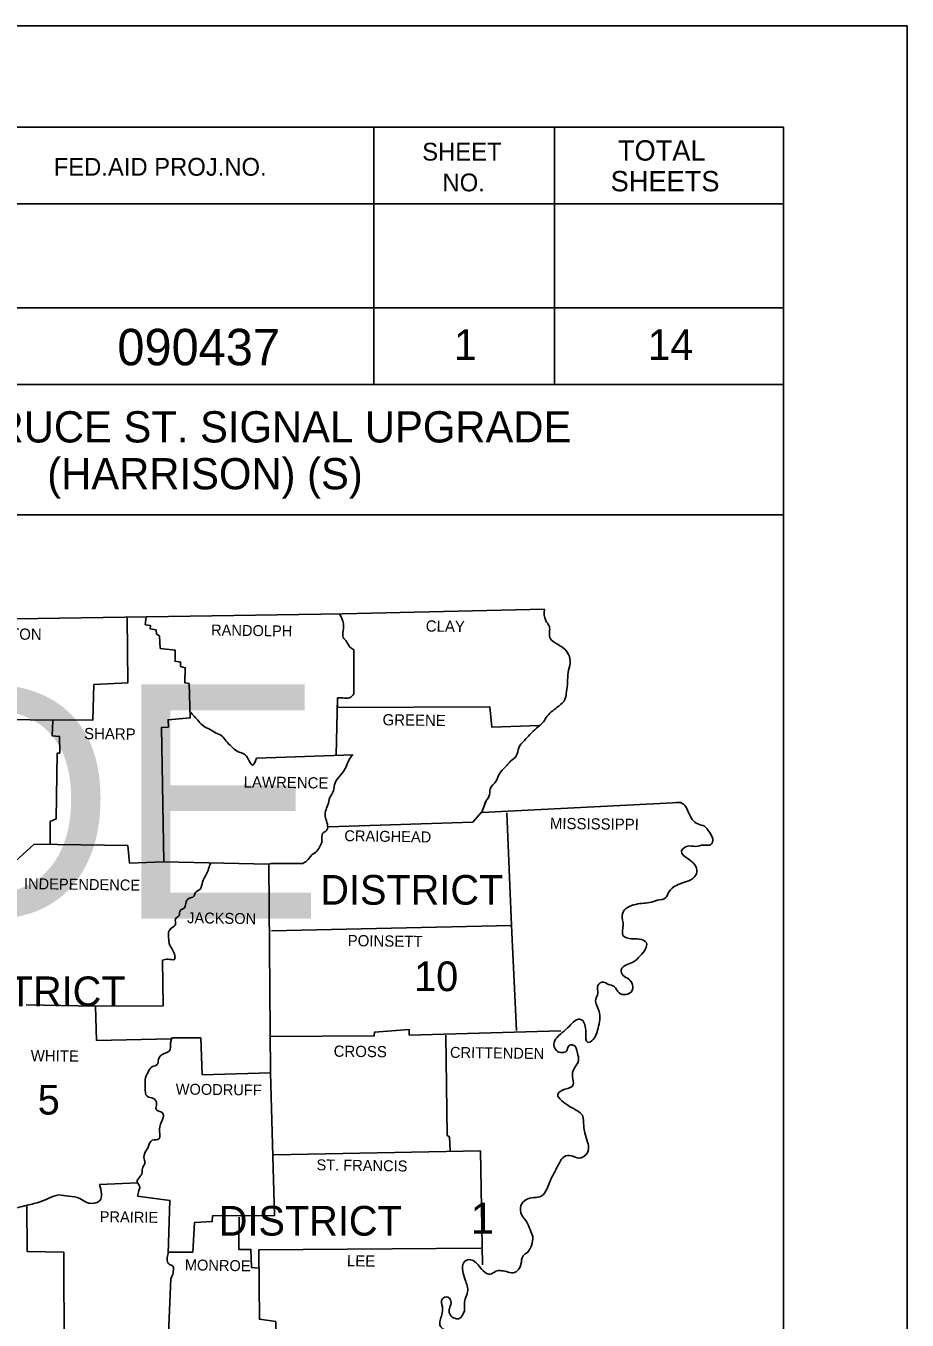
# Model space of a CAD drawing. Extents: x 19118 to 454486, y 1325406 to 1693506.
# Drawn here: x 26754.5 to 27093.1, y 1327042.2 to 1327539.3 of the extents above; entities that cross this region are included whole.
import ezdxf

# ---------------------------------------------------------------- set-up
doc = ezdxf.new("R2010")
doc.units = 0
for name, color, linetype in [('S_CURB', 7, 'Continuous'), ('S_EDGE_PAVEMENT', 7, 'Continuous'), ('S_PAVEMENT_CROWN', 7, 'Continuous'), ('S_SHOULDER', 7, 'Continuous')]:
    doc.layers.add(name, color=color, linetype=linetype)

msp = doc.modelspace()

# ---------------------------------------------------------------- linework, layer by layer
at = {"layer": 'S_CURB'}
for p, q in [((27045.61, 1327471.12), (27045.61, 1327471.12)), ((26929.76, 1327237.18), (26930.96, 1327240.88)), ((26930.06, 1327238.38), (26931.26, 1327241.28)), ((26810.56, 1327150.58), (26821.74, 1327150.58))]:
    msp.add_line(p, q, dxfattribs=at)
for points in [[(26405.17, 1327310.68), (26566.87, 1327310.58), (26708.77, 1327310.88), (26876.16, 1327313.48), (26953.76, 1327315.28)], [(26793.46, 1327312.2), (26793.66, 1327286.98), (26780.66, 1327286.28), (26780.26, 1327272.68), (26707.97, 1327273.08)], [(26800.74, 1327312.31), (26800.36, 1327309.28), (26802.36, 1327308.98), (26802.26, 1327307.78), (26804.56, 1327307.28), (26804.76, 1327305.68), (26805.86, 1327304.98), (26806.16, 1327300.18), (26811.86, 1327299.58), (26811.86, 1327295.28), (26813.96, 1327294.98), (26813.96, 1327293.28), (26815.76, 1327292.78), (26815.66, 1327286.98), (26817.26, 1327286.68), (26817.66, 1327273.58), (26809.16, 1327272.78), (26809.26, 1327269.98), (26806.66, 1327269.88), (26807.56, 1327218.28), (26847.86, 1327217.38), (26848.56, 1327137.18), (26822.26, 1327136.48), (26821.74, 1327150.58)], [(26880.56, 1327299.68), (26880.56, 1327282.78)], [(26873.74, 1327259.16), (26874.26, 1327281.18), (26874.26, 1327277.48), (26932.76, 1327277.78), (26933.56, 1327269.98), (26951.92, 1327270.65)], [(26764.86, 1327272.38), (26764.66, 1327266.58), (26767.46, 1327266.38), (26767.56, 1327259.98), (26766.56, 1327259.98), (26766.16, 1327234.78), (26763.86, 1327233.78), (26763.86, 1327224.9)], [(26843.16, 1327258.08), (26880.26, 1327259.38)], [(26929.76, 1327237.18), (27005.66, 1327241.08)], [(26870.76, 1327231.68), (26926.26, 1327233.48), (26929.56, 1327237.28)], [(26939.36, 1327237.08), (26941.06, 1327193.78), (26943.06, 1327153.48)], [(26746.27, 1327214.68), (26757.66, 1327224.98), (26793.66, 1327224.48), (26794.36, 1327217.78), (26807.46, 1327218.28)], [(26860.96, 1327217.58), (26848.76, 1327217.58), (26847.86, 1327217.38)], [(26941.06, 1327193.78), (26848.96, 1327191.68)], [(26807.06, 1327180.48), (26807.26, 1327162.88), (26781.26, 1327162.78), (26754.57, 1327163.28)], [(26781.26, 1327162.78), (26781.66, 1327149.68), (26810.46, 1327150.2)], [(26848.44, 1327151.18), (26888.36, 1327151.38), (26888.46, 1327152.78), (26901.86, 1327153.78), (26901.86, 1327151.68), (26960.06, 1327153.28)], [(26915.86, 1327151.68), (26916.36, 1327113.18), (26917.26, 1327112.58), (26917.56, 1327107.38)], [(26915.86, 1327151.68), (26916.36, 1327113.18), (26917.26, 1327112.58), (26917.56, 1327107.38)], [(26915.86, 1327151.68), (26916.36, 1327113.18), (26917.26, 1327112.58), (26917.56, 1327107.38)], [(26915.86, 1327151.68), (26916.36, 1327113.18), (26917.26, 1327112.58), (26917.56, 1327107.38)], [(26915.86, 1327151.68), (26916.36, 1327113.18), (26917.26, 1327112.58), (26917.56, 1327107.38)], [(26810.56, 1327150.58), (26810.06, 1327148.78)], [(26848.56, 1327137.18), (26850.06, 1327082.38), (26826.26, 1327082.28), (26826.16, 1327080.08), (26819.26, 1327079.68), (26818.66, 1327068.28), (26809.18, 1327068.28)], [(26849.76, 1327105.68), (26929.16, 1327107.28)], [(26929.16, 1327107.28), (26929.96, 1327063.48)], [(26929.16, 1327107.28), (26929.96, 1327063.48)], [(26929.16, 1327107.28), (26929.96, 1327063.48)], [(26929.16, 1327107.28), (26929.96, 1327063.48)], [(26929.16, 1327107.28), (26929.96, 1327063.48)], [(26929.16, 1327107.28), (26929.96, 1327063.48)], [(26929.16, 1327107.28), (26929.96, 1327063.48)], [(26929.16, 1327107.28), (26929.96, 1327063.48)], [(26782.86, 1327094.28), (26797.36, 1327094.98)], [(26754.87, 1327086.48), (26755.06, 1327068.58), (26769.16, 1327068.28), (26769.26, 1327029.88)], [(26797.36, 1327089.78), (26809.86, 1327088.18), (26809.16, 1327067.78)], [(26836.46, 1327081.78), (26836.36, 1327069.38), (26840.96, 1327069.38), (26841.16, 1327062.48), (26844.06, 1327062.18)], [(26848.46, 1326980.38), (26857.56, 1326981.18), (26857.46, 1327001.48), (26850.16, 1327001.98), (26850.56, 1327041.68), (26844.26, 1327042.58), (26844.06, 1327069.28), (26929.36, 1327069.88)], [(26810.26, 1327058.18), (26809.06, 1327030.78), (26800.86, 1327029.88), (26801.06, 1327021.78), (26804.36, 1327021.88), (26804.46, 1327019.08), (26808.96, 1327018.58), (26809.11, 1327013.76)]]:
    msp.add_lwpolyline(points, dxfattribs=at)
for points in [[(26953.76, 1327315.28), (26954.26, 1327310.88), (26955.66, 1327308.58), (26955.86, 1327304.38), (26957.56, 1327302.58), (26960.46, 1327300.78), (26963.06, 1327297.88), (26963.66, 1327294.48), (26962.86, 1327290.98), (26962.66, 1327287.08), (26962.26, 1327283.68), (26961.66, 1327280.58), (26959.26, 1327278.08), (26956.96, 1327276.28), (26954.86, 1327274.18), (26953.36, 1327271.98), (26950.76, 1327269.58), (26948.16, 1327267.08), (26946.06, 1327264.88), (26943.96, 1327262.08), (26942.96, 1327258.98), (26940.66, 1327256.78), (26938.86, 1327254.78), (26936.46, 1327252.08), (26935.26, 1327249.38), (26932.96, 1327246.28), (26932.46, 1327243.28), (26930.96, 1327240.88), (26930.86, 1327240.48)], [(26875.02, 1327313.53), (26876.56, 1327309.68), (26876.46, 1327306.98), (26876.46, 1327304.48), (26877.76, 1327302.78), (26879.06, 1327300.68), (26880.56, 1327299.68)], [(26880.56, 1327282.78), (26878.86, 1327281.18), (26876.36, 1327281.18), (26874.26, 1327281.18)], [(26817.54, 1327275.89), (26820.96, 1327272.18), (26822.86, 1327270.28), (26825.06, 1327269.18), (26827.66, 1327267.68), (26829.96, 1327266.48), (26831.46, 1327264.58), (26833.56, 1327262.48), (26835.66, 1327260.78), (26838.96, 1327259.18), (26840.06, 1327257.48), (26841.56, 1327255.38), (26843.16, 1327258.08)], [(26879.96, 1327259.28), (26878.46, 1327256.88), (26877.26, 1327254.08), (26874.86, 1327250.88), (26873.06, 1327247.78), (26872.76, 1327245.68), (26871.36, 1327242.88), (26870.56, 1327240.08), (26869.66, 1327237.68), (26869.66, 1327235.18), (26870.36, 1327232.68), (26870.16, 1327230.38), (26868.66, 1327229.28), (26868.26, 1327226.38), (26867.66, 1327224.38), (26866.36, 1327222.38), (26864.46, 1327220.88), (26862.46, 1327218.58), (26860.96, 1327217.58)], [(27004.56, 1327240.98), (27005.66, 1327241.08), (27009.06, 1327237.48), (27010.56, 1327234.48), (27012.76, 1327232.78), (27015.26, 1327231.88), (27017.16, 1327229.58), (27018.46, 1327227.08), (27017.76, 1327224.88), (27014.96, 1327224.68), (27011.86, 1327224.18), (27008.86, 1327224.28), (27006.46, 1327222.28), (27008.66, 1327219.58), (27011.56, 1327217.08), (27012.36, 1327214.38), (27010.76, 1327211.78), (27007.56, 1327210.38), (27004.46, 1327209.18), (27001.66, 1327206.78), (27000.36, 1327204.48), (26997.26, 1327203.48), (26994.06, 1327202.58), (26991.26, 1327202.28), (26988.06, 1327201.68), (26984.96, 1327200.18), (26983.66, 1327197.58), (26984.06, 1327193.88), (26983.96, 1327189.98), (26987.26, 1327188.68), (26990.16, 1327188.58), (26992.96, 1327187.08), (26992.66, 1327184.88), (26990.56, 1327182.08), (26988.06, 1327179.88), (26985.56, 1327178.78), (26983.26, 1327176.68), (26984.06, 1327174.58), (26986.16, 1327173.18), (26987.66, 1327170.88), (26987.46, 1327168.78), (26985.06, 1327167.28), (26982.46, 1327167.88), (26980.56, 1327170.38), (26978.36, 1327171.18), (26976.46, 1327172.08), (26974.26, 1327170.78), (26974.26, 1327167.88), (26973.46, 1327164.78), (26974.16, 1327162.48), (26975.06, 1327159.28), (26974.96, 1327156.88), (26974.16, 1327153.48), (26972.46, 1327149.98), (26970.46, 1327148.88), (26969.66, 1327152.68), (26969.26, 1327155.78), (26968.06, 1327157.58), (26966.46, 1327157.68), (26964.36, 1327156.18), (26962.06, 1327153.88), (26959.16, 1327151.38), (26957.46, 1327148.88), (26958.36, 1327145.78), (26960.56, 1327144.98), (26962.26, 1327145.58), (26963.16, 1327147.58), (26964.86, 1327147.88), (26966.46, 1327144.78)], [(26825.53, 1327217.84), (26823.76, 1327213.38), (26822.36, 1327210.38), (26821.46, 1327207.78), (26819.56, 1327206.28), (26818.96, 1327204.88), (26817.26, 1327204.28), (26815.96, 1327202.28), (26815.36, 1327200.48), (26813.96, 1327199.68), (26813.26, 1327197.48), (26811.96, 1327196.28), (26812.06, 1327194.28), (26810.56, 1327192.88), (26809.36, 1327191.28), (26809.36, 1327189.08), (26809.86, 1327186.18), (26810.86, 1327184.48), (26811.76, 1327182.28), (26811.66, 1327180.88), (26809.16, 1327180.88), (26807.06, 1327180.48)], [(26810.06, 1327148.78), (26809.56, 1327145.48), (26807.66, 1327144.58), (26805.46, 1327142.38), (26804.96, 1327140.38), (26803.16, 1327139.58), (26801.46, 1327137.48), (26800.36, 1327134.58), (26800.36, 1327131.58), (26801.06, 1327128.18), (26803.56, 1327127.28), (26804.76, 1327125.28), (26804.56, 1327123.18), (26806.96, 1327121.78), (26807.36, 1327120.58), (26806.96, 1327119.28), (26805.86, 1327115.58), (26805.96, 1327113.08), (26805.76, 1327111.98), (26803.06, 1327111.28), (26801.46, 1327108.58), (26800.36, 1327106.68), (26799.96, 1327104.18), (26800.26, 1327102.38), (26799.46, 1327100.98), (26799.16, 1327098.88), (26798.16, 1327097.08), (26797.26, 1327095.38), (26798.26, 1327093.38), (26797.96, 1327091.98), (26797.36, 1327089.78)], [(26966.46, 1327144.78), (26966.86, 1327141.88), (26965.16, 1327138.78), (26964.56, 1327135.68), (26964.86, 1327132.58), (26961.66, 1327130.88), (26958.86, 1327128.88), (26960.46, 1327126.48), (26963.46, 1327124.28), (26966.46, 1327122.58), (26968.36, 1327120.88), (26968.86, 1327116.78), (26969.36, 1327114.18), (26970.36, 1327110.58), (26970.76, 1327108.08), (26968.96, 1327105.08), (26966.86, 1327104.48), (26964.66, 1327105.18), (26962.06, 1327105.38), (26959.96, 1327103.38), (26958.46, 1327100.58), (26956.96, 1327097.78), (26955.86, 1327095.38), (26954.76, 1327092.78), (26952.56, 1327089.78), (26949.86, 1327089.28), (26946.66, 1327088.48), (26944.76, 1327086.28), (26945.06, 1327082.58), (26946.86, 1327080.08), (26948.26, 1327076.98), (26949.26, 1327074.28), (26948.76, 1327070.88), (26947.36, 1327068.38), (26945.56, 1327066.88), (26944.76, 1327063.68), (26943.46, 1327061.28), (26942.26, 1327060.48), (26939.86, 1327060.68), (26937.26, 1327061.18), (26935.06, 1327060.98), (26932.96, 1327059.88), (26930.86, 1327060.58), (26928.66, 1327062.98), (26926.86, 1327064.78), (26924.86, 1327065.48), (26922.76, 1327064.38), (26922.36, 1327061.08), (26923.36, 1327057.68), (26924.26, 1327053.08), (26923.36, 1327050.28), (26923.06, 1327045.68)], [(26715.57, 1327090.28), (26721.17, 1327090.48), (26726.67, 1327090.68), (26730.17, 1327089.68), (26734.17, 1327088.38), (26738.87, 1327087.78), (26742.17, 1327086.48), (26746.07, 1327084.48), (26751.07, 1327085.38), (26754.97, 1327086.38), (26760.06, 1327087.68), (26763.36, 1327089.08), (26767.16, 1327090.28), (26770.96, 1327089.78), (26775.26, 1327088.98), (26777.96, 1327087.38), (26782.86, 1327088.08), (26782.86, 1327094.28)], [(26809.16, 1327067.78), (26808.76, 1327065.78), (26809.56, 1327063.68), (26810.96, 1327062.98), (26811.16, 1327060.98), (26810.66, 1327058.98), (26810.26, 1327058.18)], [(26923.06, 1327045.68), (26920.76, 1327042.78), (26917.36, 1327044.58), (26917.36, 1327046.98), (26917.86, 1327049.48), (26916.66, 1327051.08), (26914.56, 1327050.38), (26914.56, 1327047.28), (26914.36, 1327044.28), (26913.76, 1327039.98), (26915.16, 1327038.68), (26918.36, 1327038.28), (26920.66, 1327037.68), (26922.06, 1327035.38), (26921.96, 1327032.58), (26920.86, 1327029.88), (26919.26, 1327027.68), (26916.76, 1327026.88), (26914.76, 1327028.18), (26913.96, 1327030.78), (26913.06, 1327033.08), (26911.36, 1327034.78), (26909.56, 1327032.88), (26909.16, 1327029.38), (26909.26, 1327026.38), (26909.26, 1327022.28), (26911.86, 1327019.58), (26913.46, 1327016.48), (26912.96, 1327013.68), (26911.06, 1327010.38), (26910.26, 1327007.48), (26909.46, 1327003.58), (26909.56, 1326999.28), (26908.86, 1326995.08), (26907.46, 1326992.28), (26904.86, 1326989.98), (26903.16, 1326988.48), (26901.76, 1326986.98), (26901.06, 1326983.98), (26900.56, 1326981.88), (26898.66, 1326979.38), (26897.16, 1326979.18), (26895.96, 1326980.18), (26895.56, 1326981.88), (26895.56, 1326983.58), (26894.76, 1326985.28), (26892.26, 1326985.98), (26890.26, 1326985.88), (26889.36, 1326984.48), (26890.66, 1326980.58), (26891.16, 1326978.08), (26890.46, 1326974.68), (26890.86, 1326974.28), (26887.26, 1326972.38), (26884.36, 1326972.08), (26881.96, 1326971.38), (26879.66, 1326969.88), (26878.56, 1326967.68), (26876.96, 1326965.88), (26875.56, 1326964.18), (26873.66, 1326963.38), (26871.56, 1326963.78), (26868.76, 1326964.08), (26867.16, 1326962.08), (26867.66, 1326959.18), (26869.56, 1326957.48), (26872.36, 1326956.68), (26875.26, 1326956.88), (26878.06, 1326957.18), (26880.66, 1326955.78), (26880.16, 1326953.08), (26877.66, 1326951.78), (26873.96, 1326951.38), (26870.96, 1326951.68), (26867.36, 1326950.88), (26865.56, 1326948.58), (26866.56, 1326945.08), (26870.46, 1326943.68), (26872.26, 1326940.38), (26872.36, 1326937.28), (26871.06, 1326933.18), (26869.26, 1326931.28), (26865.76, 1326930.48), (26863.06, 1326929.98), (26862.66, 1326925.38), (26861.46, 1326923.08), (26859.36, 1326922.38), (26856.36, 1326923.88), (26854.56, 1326924.58), (26852.36, 1326925.58), (26849.56, 1326927.28), (26847.46, 1326926.98), (26848.06, 1326922.58), (26848.26, 1326922.38), (26850.66, 1326919.08), (26853.06, 1326916.48), (26854.16, 1326913.38)]]:
    msp.add_spline(points, degree=3, dxfattribs=at)
at = {"layer": 'S_EDGE_PAVEMENT'}
msp.add_lwpolyline([(23759.74, 1327539.29), (27093.14, 1327539.29), (27093.14, 1325405.92), (23759.74, 1325405.92)], close=True, dxfattribs=at)
at = {"layer": 'S_SHOULDER'}
for p, q in [((23883.81, 1327500.35), (27045.61, 1327500.35)), ((26888.21, 1327500.35), (26888.21, 1327401.55)), ((26957.61, 1327500.35), (26957.61, 1327401.55)), ((27045.61, 1325445.75), (27045.61, 1327500.35)), ((27045.61, 1327470.95), (26614.61, 1327470.95)), ((27045.61, 1327471.15), (27045.61, 1327471.15)), ((27045.61, 1327430.95), (26614.61, 1327430.95)), ((26644.21, 1327430.95), (27045.61, 1327430.95)), ((27045.61, 1327401.55), (26223.01, 1327401.55)), ((26614.61, 1327351.45), (27045.61, 1327351.45))]:
    msp.add_line(p, q, dxfattribs=at)

# ---------------------------------------------------------------- texts
at = {"layer": 'S_CURB'}
for s, height, p in [('1', 11.72, (26919.02, 1327411.01)), ('14', 11.724, (26993.48, 1327411.01)), ('MAIN ST.   SPRUCE ST. SIGNAL UPGRADE', 89.9998, (24421.67, 1327196.45)), ('DISTRICT', 11.4, (26867.66, 1327201.78)), ('10', 11.4, (26903.69, 1327168.58)), ('DISTRICT', 11.4, (26722.52, 1327162.8)), ('5', 11.4, (26759.06, 1327121.18)), ('DISTRICT', 11.4, (26828.66, 1327074.68)), ('1', 12, (26925.46, 1327075.38))]:
    msp.add_text(s, height=height, dxfattribs=at).set_placement(p)
for s, height, rotation, p in [('CLAY', 4.299, 359.2258, (26908.16, 1327306.68)), ('FULTON', 4.3, 359.4996, (26737.57, 1327303.68)), ('RANDOLPH', 4.201, 359.2583, (26825.66, 1327305.18)), ('GREENE', 4.301, 359.2361, (26891.56, 1327270.68)), ('SHARP', 4.3, 359.3905, (26776.86, 1327265.38)), ('LAWRENCE', 4.301, 359.2678, (26838.16, 1327246.78)), ('CRAIGHEAD', 4.201, 359.1159, (26876.86, 1327226.18)), ('MISSISSIPPI', 4.2995, 359.3097, (26955.86, 1327230.88)), ('INDEPENDENCE', 4.1993, 359.2187, (26753.77, 1327207.78)), ('JACKSON', 4.199, 359.1352, (26816.46, 1327194.68)), ('POINSETT', 4.3, 359.1987, (26878.16, 1327185.88)), ('WHITE', 4.301, 359.3139, (26756.36, 1327141.68)), ('CROSS', 4.3, 359.3839, (26872.76, 1327143.38)), ('CRITTENDEN', 4.201, 359.213, (26917.46, 1327142.98)), ('WOODRUFF', 4.199, 359.2748, (26812.06, 1327128.88)), ('ST. FRANCIS', 4.1993, 359.2216, (26866.16, 1327099.78)), ('PRAIRIE', 4.2, 359.2116, (26782.86, 1327079.88)), ('LEE', 4.301, 359.4327, (26877.86, 1327062.88)), ('MONROE', 4.199, 359.0331, (26815.56, 1327061.38))]:
    msp.add_text(s, height=height, rotation=rotation, dxfattribs=at).set_placement(p)
at = {"layer": 'S_PAVEMENT_CROWN'}
for s, p in [('MAIN ST./SPRUCE ST. SIGNAL UPGRADE', (26646.7, 1327379.3)), ('(HARRISON) (S)', (26762.73, 1327361.3))]:
    msp.add_text(s, height=12, dxfattribs=at).set_placement(p)
at = {"layer": 'S_SHOULDER'}
for s, height, p in [('SHEET', 6.84, (26906.81, 1327487.55)), ('TOTAL', 7.819, (26982.01, 1327487.55)), ('FED.AID PROJ.NO.', 6.84, (26765.21, 1327481.75)), ('NO.', 6.84, (26914.61, 1327475.75)), ('SHEETS', 7.819, (26979.21, 1327475.75)), ('090437', 14, (26789.68, 1327408.94))]:
    msp.add_text(s, height=height, dxfattribs=at).set_placement(p)

doc.saveas('drawing.dxf')
